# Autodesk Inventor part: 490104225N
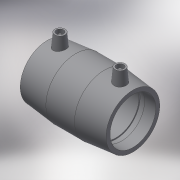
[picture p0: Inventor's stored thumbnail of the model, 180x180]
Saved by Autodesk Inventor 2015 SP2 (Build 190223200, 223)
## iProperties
Created: 2017-06
Part Number: 490104225N
Material: Generic
Description: PLASSON COUPLER 225-225
Document SubType Name: Modeling
Designer: KIM
Mass: 3584.05 g
Surface Area: 4077.86 cm^2
Volume: 3584.05 cm^3
Density: 1 g/cm^3
Appearance: Default
Author: KIM
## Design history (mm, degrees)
derived "490104.ipt"
feature "Solid1::490104.ipt"
tag "TaggingFeature1"
body "Solid1"
other parameters: "d1" = 225, "d2" = 272, "d3" = 119, "d5" = 244.8, "d6" = 213.75, "d7" = 225, "d8" = 168 deg, "d10" = 47.6, "d11" = 15.86667, "d14" = 17.6296, "d15" = 119, "d16" = 119, "d17" = 213.75, "d18" = 225, "d19" = 3.52592, "d20" = 168 deg, "d22" = 255.68, "d23" = 272, "d24" = 248.0096, "d25" = 135 deg, "d27" = 135 deg, "d29" = 138, "d30" = 14, "d31" = 84, "d34" = 5 deg, "d35" = 15, "d39" = 5 deg, "d41" = 4, "d42" = 14, "d43" = 0, "d45" = 4, "d46" = 14, "d47" = 0, "d48" = 3, "d49" = 0, "d50" = 3, "d51" = 0, "d52" = 34.51, "d53" = 8.6275, "d_" = 225, "L_1" = 119, "D_" = 272, "A_" = 138, "d_2" = 12
